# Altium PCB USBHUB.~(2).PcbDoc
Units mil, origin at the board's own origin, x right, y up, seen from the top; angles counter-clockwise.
Board outline 6000 x 4000 mil, 2 copper layers (Top Layer, Bottom Layer); 37 components, 24 nets, 134 pads, 0 vias.
Unrouted connection lines stored in the file: 91.
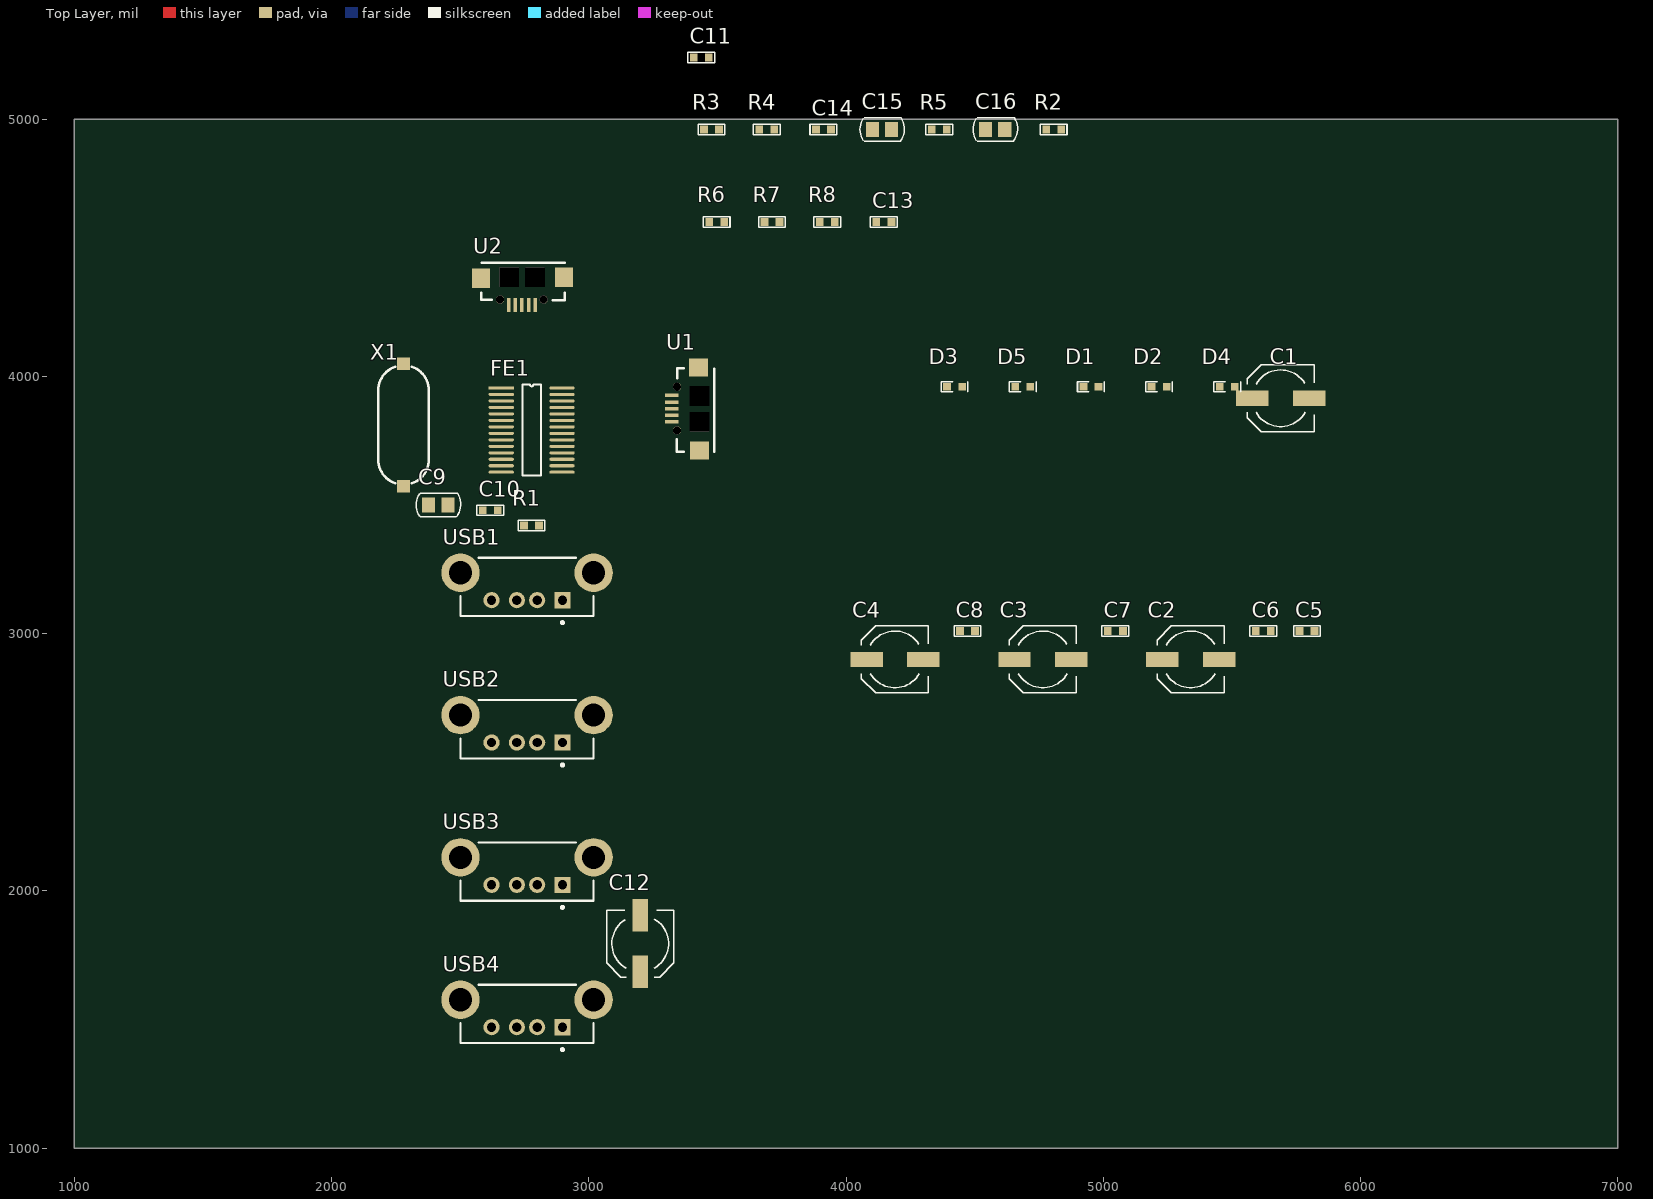
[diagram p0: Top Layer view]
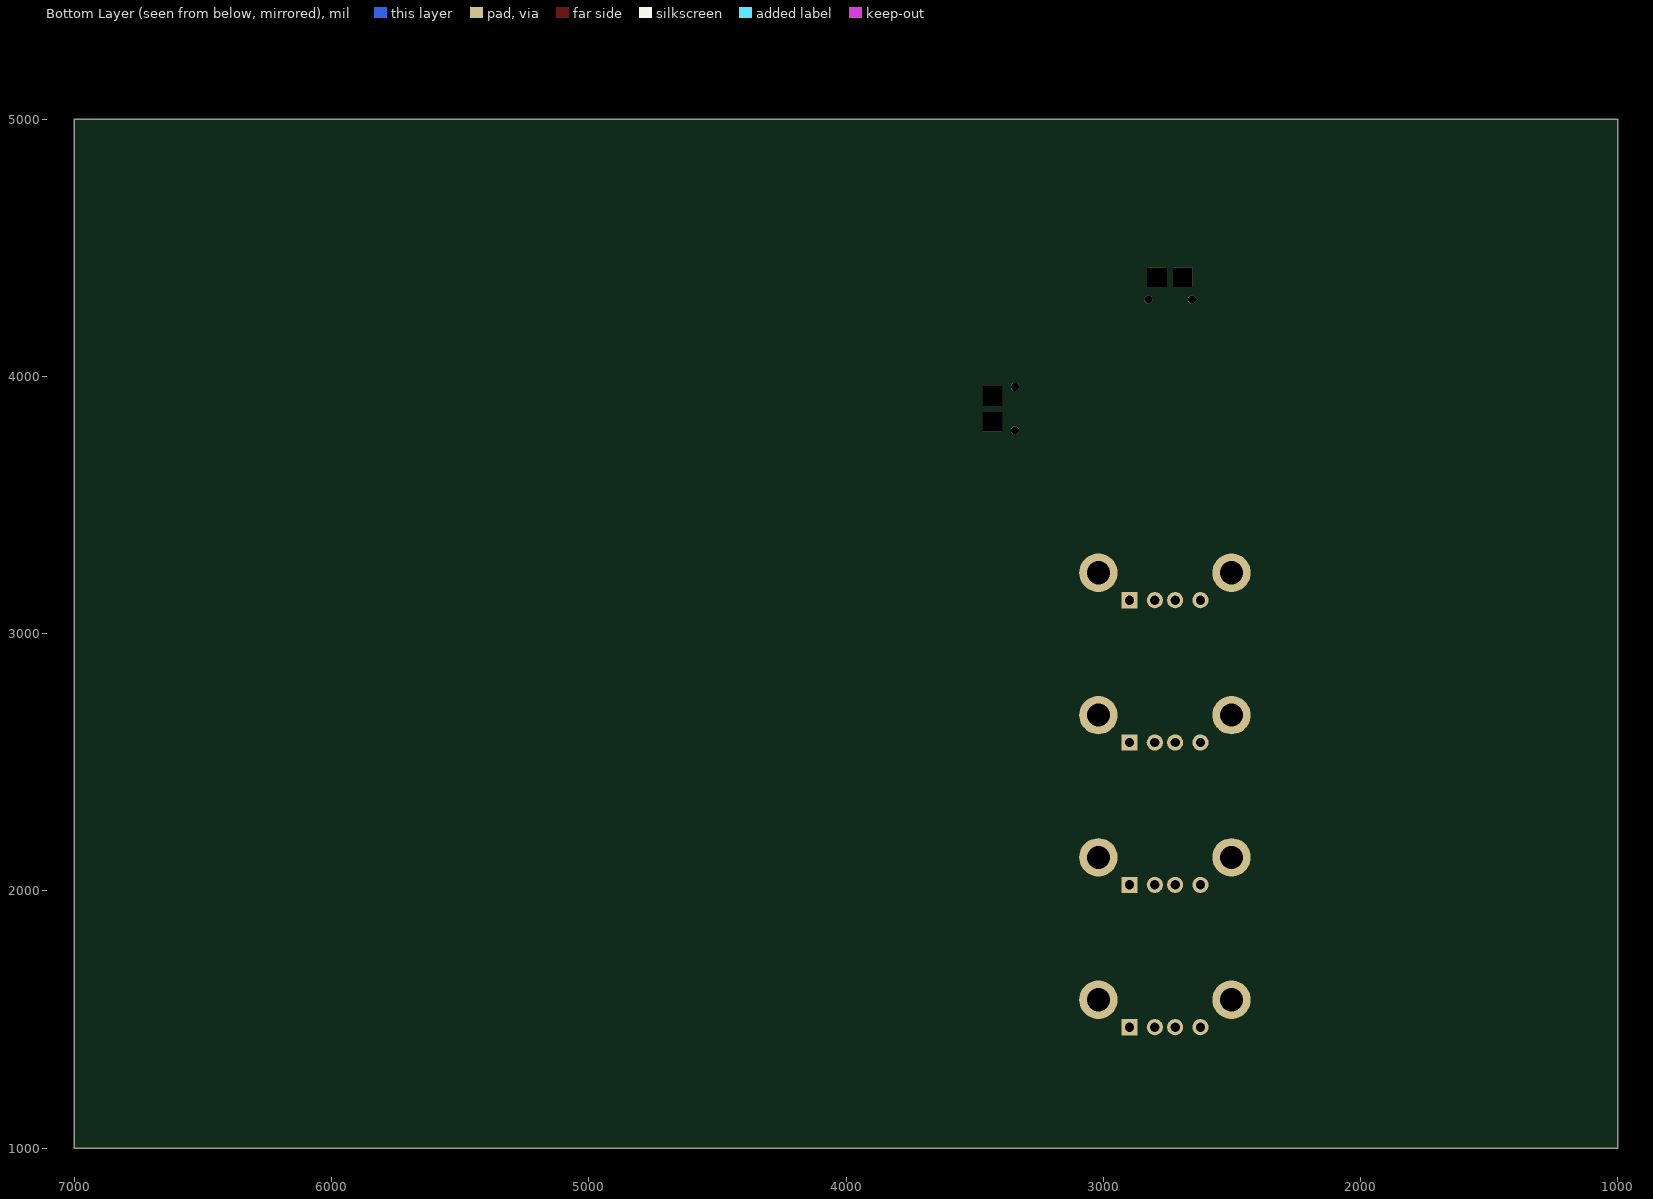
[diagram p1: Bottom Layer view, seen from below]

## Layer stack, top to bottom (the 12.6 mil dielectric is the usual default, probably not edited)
Top Layer: signal copper 1.4
Dielectric: dielectric 12.6, FR-4, Dk 4.8
Bottom Layer: signal copper 1.4

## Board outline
1000,1000 7000,1000 7000,5000 1000,5000

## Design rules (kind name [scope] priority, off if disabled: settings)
Clearance [All] p1: gap=10
PolygonConnect [All] p1: connectstyle=Relief reliefconductorwidth=10 reliefentries=4 polygonreliefangle="90 Angle"
RoomDefinition USBHUB [InComponentClass('USBHUB')] p1: confinementstyle=ConfineIn formatcopy=TRUE lockcomponents=FALSE outline 0,0 2000,0 2000,1000 0,1000
RoutingVias [All] p1: holewidth=28 width=50 viastyle="Through Hole" minholewidth=28 minwidth=50 maxholewidth=28 maxwidth=50
SilkscreenOverComponentPads [All] p1: minsilkscreentomaskgap=10
SolderMaskExpansion [All] p1: expansion=4
TestPointUsage [All] p1: valid=0 allowmultiple=FALSE
Testpoint [All] p1: side=15 testpointundercomponent=TRUE minsize=40 maxsize=100 preferedsize=60 minholesize=0 maxholesize=40 preferedholesize=32 testpointgrid=1 style=1023 order=0123456789
Width [All] p1: maxlimit=10 minlimit=10 preferedwidth=10
23 further rules are at their usual default settings.

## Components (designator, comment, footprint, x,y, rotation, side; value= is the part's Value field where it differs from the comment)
C1 "Cap_Pol" cap_220uF/16V 5690,3915 r0 top
C2 "Cap_Pol" cap_220uF/16V 5340,2900 r0 top
C3 "Cap_Pol" cap_220uF/16V 4765,2900 r0 top
C4 "Cap_Pol" cap_220uF/16V 4190,2900 r0 top
C5 "Cap1" 0603 5790,3010 r0 top
C6 "Cap1" 0603 5620,3010 r0 top
C7 "Cap1" 0603 5045,3010 r0 top
C8 "Cap1" 0603 4470,3010 r0 top
C9 "Cap1" 2012[0805]-C 2415,3500 r0 top
C10 "Cap1" 0603 2615,3480 r0 top
C11 "Cap1" 0603 3435,5240 r0 top
C12 "Cap_Pol" cap_220uF/16V 3200,1795 r90 top
C13 "Cap1" 0603 4145,4600 r0 top
C14 "Cap1" 0603 3910,4960 r0 top
C15 "Cap1" 2012[0805]-C 4140,4960 r0 top
C16 "Cap1" 2012[0805]-C 4580,4960 r0 top
D1 "LED" 0603-Polar 4950,3960 r0 top
D2 "LED" 0603-Polar 5215,3960 r0 top
D3 "LED" 0603-Polar 4420,3960 r0 top
D4 "LED" 0603-Polar 5480,3960 r0 top
D5 "LED" 0603-Polar 4685,3960 r0 top
FE1 "FE1.1s" SSOP-28 2660,3955 r0 top
R1 "Res1" 0603 2775,3420 r0 top
R2 "Res1" 0603 4805,4960 r0 top
R3 "Res1" 0603 3475,4960 r0 top
R4 "Res1" 0603 3690,4960 r0 top
R5 "Res1" 0603 4360,4960 r0 top
R6 "Res1" 0603 3495,4600 r0 top
R7 "Res1" 0603 3710,4600 r0 top
R8 "Res1" 0603 3925,4600 r0 top
U1 "Micro-USB" Micro-USB 3320,3875 r90 top
U2 "Micro-USB" Micro-USB 2740,4275 r180 top
USB1 "USB" USB2.5-2V4A 2760,3295 r90 top
USB2 "USB" USB2.5-2V4A 2760,2741.67 r90 top
USB3 "USB" USB2.5-2V4A 2760,2188.33 r90 top
USB4 "USB" USB2.5-2V4A 2760,1635 r90 top
X1 "12M" XTAL_SMD 2280,3715 r90 top

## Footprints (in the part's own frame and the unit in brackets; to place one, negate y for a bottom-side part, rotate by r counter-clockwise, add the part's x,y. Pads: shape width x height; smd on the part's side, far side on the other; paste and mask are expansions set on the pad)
0603 [mil]
  rect 30x30 smd: 1(-27,0) 2(31.5,0)
  silkscreen extent -50,-20 54,20
0603-Polar [mil]
  rect 30x30 smd: 1(-27,0) 2(31.5,0)
  silkscreen extent -50,-20 54,20
2012[0805]-C [mm] "Chip Resistor; Body 2.0 x 1.3 mm (LxW typ)"
  rect 1.3x1.5 smd: 1(-0.95,0) 2(0.95,0)
  silkscreen extent -2.17,-1.16 2.21,1.14
cap_220uF/16V [mm]
  rect 3.2x1.5 smd: 1(-2.794,0) 2(2.8,0)
  silkscreen extent -3.3,-3.3 3.3,3.3
Micro-USB [mm]
  rect 1.8x1.9 smd: 0(-4.15,-2.8) 0(4.05,-2.7)
  round 0.8 hole 0.8: 0(-2.15,-0.6) 0(2.15,-0.6)
  rect 1.9x1.9 hole 1.9 square: 0(-1.3,-2.8) 0(1.25,-2.8)
  rect 0.35x1.35 smd: 1(-1.308,-0.062) 2(-0.657,-0.062) 3(-0.008,-0.062) 4(0.643,-0.062) 5(1.292,-0.062)
  silkscreen extent -4.25,-4.25 4,-0.55
SSOP-28 [mm]
  rect 2.5x0.3 smd: 1(0,0)
  oval 2.5x0.3 smd: 2(0,-0.64) 3(0,-1.28) 4(0,-1.92) 5(0,-2.56) 6(0,-3.2) 7(0,-3.84) 8(0,-4.48) 9(0,-5.12) 10(0,-5.76) 11(0,-6.4) 12(0,-7.04) 13(0,-7.68) 14(0,-8.32) 15(6,-8.32) 16(6,-7.68) 17(6,-7.04) 18(6,-6.4) 19(6,-5.76) 20(6,-5.12) 21(6,-4.48) 22(6,-3.84) 23(6,-3.2) 24(6,-2.56) 25(6,-1.92) 26(6,-1.28) 27(6,-0.64) 28(6,0)
  silkscreen extent 2.08,-8.64 3.92,0.32
USB2.5-2V4A [mm] "Connector; USB1.1, Type A, Thru-Hole; 4 Position; Vertical"
  rect 1.6x1.6 hole 0.92: 1(-4.19,-3.5)
  round 1.6 hole 0.92: 2(-4.19,-1) 3(-4.19,1) 4(-4.19,3.5)
  round 3.8 hole 2.3: 5(-1.48,6.57) 6(-1.48,-6.57)
  silkscreen extent -6.53,-6.57 0,6.57, body extent -5.76,-6.57 0,6.57, height 15
XTAL_SMD [mil]
  rect 50x50 smd: 1(-142.13,0) 2(334.25,0)
  silkscreen extent -131,-98 323,98

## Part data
C1 C2 C3 C4 C5 C6 C7 C8 C9 C10 C11 C12 C13 C14 C15 C16: "Capacitor"
D1 D2 D3 D4 D5: library part LED1, "Typical INFRARED GaAs LED"
R1 R2 R3 R4 R5 R6 R7 R8: "Resistor"
X1: library part XTAL_1, "Crystal Oscillator"

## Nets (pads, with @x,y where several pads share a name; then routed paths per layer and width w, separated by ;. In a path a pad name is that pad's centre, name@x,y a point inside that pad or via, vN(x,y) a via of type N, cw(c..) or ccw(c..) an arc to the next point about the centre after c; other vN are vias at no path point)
GND: C1.1 C2.1 C3.1 C4.1 C5.1 C6.1 C7.1 C8.1 C9.1 C10.1 C11.1 C12.1 C13.2 C14.1 C15.1 C16.1 R1.1 R4.1 R6.1 U1.4 U1.5 U2.4 U2.5 USB1.4 USB1.5 USB1.6 USB2.4 USB2.5 USB2.6 USB3.4 USB3.5 USB3.6 USB4.4 USB4.5 USB4.6
NetD1_1: D1.1 D2.1 D3.2 D4.1 D5.2 FE1.22
NetD1_2: D1.2 R6.2
NetD2_2: D2.2 D3.1 R7.2
NetD4_2: D4.2 D5.1 R8.2
NetFE1_4: FE1.4 USB1.2
NetFE1_5: FE1.5 USB1.3
NetFE1_6: FE1.6 USB2.2
NetFE1_7: FE1.7 USB2.3
NetFE1_8: FE1.8 USB3.2
NetFE1_9: FE1.9 USB3.3
NetFE1_10: FE1.10 USB4.2
NetFE1_11: FE1.11 USB4.3
NetFE1_14: FE1.14 R1.2
NetFE1_15: FE1.15 U1.2 U2.2
NetFE1_16: FE1.16 U1.3 U2.3
NetFE1_17: FE1.17 R3.1
NetFE1_18: FE1.18 R4.2 R5.1
NetFE1_19: FE1.19 R2.1
NetFE1_23: FE1.23 R8.1
NetFE1_24: FE1.24 R7.1
VCC1_8: C9.2 C13.1 FE1.12 FE1.28
VCC3_3: C10.2 C16.2 FE1.13 FE1.21 FE1.26 R2.2 R3.2
VCC5: C1.2 C2.2 C3.2 C4.2 C5.2 C6.2 C7.2 C8.2 C11.2 C12.2 C14.2 C15.2 FE1.20 R5.2 U1.1 U2.1 USB1.1 USB2.1 USB3.1 USB4.1
pads on no net: FE1.1 FE1.2 FE1.3 FE1.25 FE1.27 U1.0 U2.0 X1.1 X1.2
